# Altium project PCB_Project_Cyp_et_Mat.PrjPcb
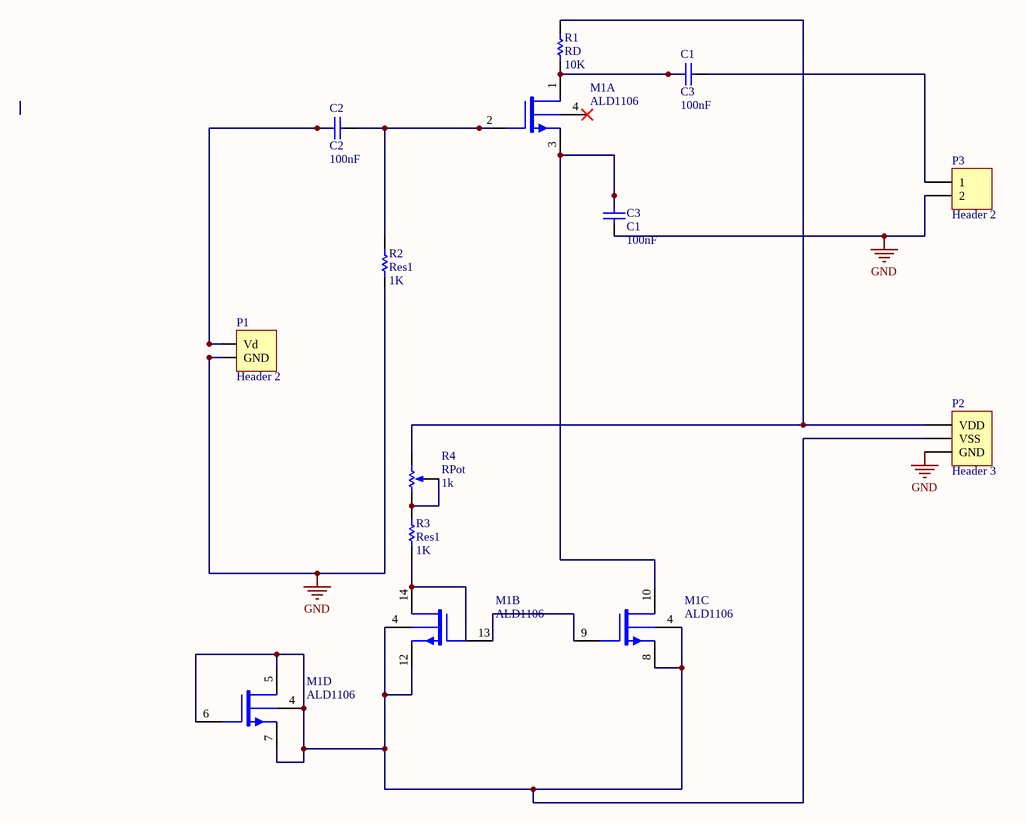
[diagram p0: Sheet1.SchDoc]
1 sheet, 11 parts. Net scope: global (net labels, ports and power ports of the same name join across sheets).
Board file: PCB2.PcbDoc

## Sheet Sheet1.SchDoc
size A4

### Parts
C1  C3  value 100nF  [RAD-0.3]
C2  C2  value 100nF  [RAD-0.3]
C3  C1  value 100nF  [RAD-0.3]
M1  ALD1106  [DIP-14]  (parts A,B,C,D of 4)
P1  Header 2  [HDR1X2]
P2  Header 3  [HDR1X3]
P3  Header 2  [HDR1X2]
R1  RD  value 10K  [AXIAL-0.3]
R2  Res1  value 1K  [AXIAL-0.3]
R3  Res1  value 1K  [AXIAL-0.3]
R4  RPot  value 1k  [VR5]

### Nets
GND: C3.1 P1.2(GND) P2.3(GND) P3.2 R2.1
NetC1_1: C1.1 M1.1(DN1) R1.1
NetC1_2: C1.2 P3.1
NetC2_1: C2.1 P1.1(Vd)
NetC2_2: C2.2 M1.2(GN1) R2.2
NetC3_2: C3.2 M1.3(SN1) M1.10(DN3)
NetM1_4: M1.4(V-) M1.5(DN4) M1.6(GN4) M1.7(SN4) M1.8(SN3) M1.12(SN2) P2.2(VSS)
NetM1_9: M1.9(GN3) M1.13(GN2)
NetM1_14: M1.14(DN2) R3.1
NetP2_1: P2.1(VDD) R1.2 R4.3(BOT)
NetR3_2: R3.2 R4.1(TOP) R4.2(TAP)

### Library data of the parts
C1-C3 = Cap: Capacitor
M1 = ALD1106: Quad N-channel matched MOSFET array
P1 P3 = Header 2: Header, 2-Pin
P2 = Header 3: Header, 3-Pin
R1-R3 = Res1: Resistor
R4 = RPot: Potentiometer; Sim Note: Enter the Resistance value and the set point into parameter fields.; Set Position: 0.5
